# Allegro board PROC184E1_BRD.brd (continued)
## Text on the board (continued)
User.21: TP26 | C479 | C459 | B | TP49 | R304 | R309 | R315 | R294 | R298 | R283 | R281 | R257 | R259 | R276 | R267 | R270 | R273 | R264 | R261 | R311 | FL26 | R258 | R302 | R275 | R268 | R282 | R1292 | R260 | FL27 | TP142 | A | TP146 | R414 | C | R428 | U77 | U70 | FL33 | FL34 | FL35 | FL24 | FL25 | FL32 | TP137 | U53 | TP166 | FL23 | TP132 | TP149 | R351 | U74 | TP191 | U66 | R541 | TP192 | U110 | TP197 | U104 | TP189 | TP152 | FL43 | TP116 | D36 | R470 | TP120 | FL44 | TP165 | TP160 | FL45 | FL42 | TP122 | C285 | FL46 | TP155 | D19 | TP239 | FL6 | D20 | FL1 | D13 | D14 | Y3 | D15 | D16 | TP256 | U137 | TP227 | TP222 | L37 | FL53 | FL50 | D | FL54 | FL51 | TP180 | TP185 | FL55 | FL52 | U129 | U95 | U85 | TP131 | TP315 | TP124 | TP128 | U96 | TP147 | TP115 | TP220 | R396 | R400 | R404 | R391 | TP205 | R386 | R378 | TP123 | C352 | TP186 | L30 | TP221 | U117 | FL47 | TP187 | C330 | C336 | TP38 | C340 | C343 | C260 | C293 | U118 | C323 | FL48 | C261 | C294 | U120 | TP225 | TP145 | TP210 | TP209 | TP218 | TP216 | TP194 | TP195 | TP181 | TP174 | TP153 | TP127 | TP150 | TP129 | TP125 | J48 | TP143 | U106 | U83 | U100 | U115 | U93 | U99 | U84 | U94 | TP251 | LD11 | U57 | U65 | U64 | U61 | U60 | U56 | U32 | U31 | TP34 | TP75 | TP35 | TP23 | TP248 | LD12 | TP224 | L29 | TP226 | Q2 | C115 | R142 | R144 | R143 | R137 | R644 | R656 | R665 | R675 | C450 | C487 | C465 | R642 | R674 | R651 | R691 | C526 | R224 | R227 | R212 | R238 | R217 | R233 | R672 | R625 | R632 | R636 | C491 | C186 | C190 | C196 | R695 | C191 | C197 | C187 | C188 | R218 | R211 | R239 | R231 | R287 | R291 | C166 | R230 | R236 | R242 | R225 | R422 | R419 | R214 | R246 | C162 | U102 | R420 | R423 | C163 | U79 | R384 | R379 | R213 | R417 | R390 | R385 | R567 | R561 | R220 | R397 | R392 | R517 | R506 | R413 | U107 | R526 | R409 | R542 | R552 | C282 | R342 | R324 | C382 | R569 | R566 | C346 | R584 | R523 | C247 | R513 | R500 | C322 | R401 | C296 | R437 | C283 | C255 | C291 | R519 | C274 | R533 | U75 | R406 | C292 | R507 | R540 | R424 | U63 | R518 | C256 | R477 | C327 | R425 | R368 | C75 | R527 | C284 | R426 | C347 | C89 | R516 | C83 | R131 | R508 | C78 | R458 | C268 | R440 | R402 | R446 | C262 | R134 | R138 | R115 | R119 | R124 | C105 | R399 | R336 | R129 | R74 | R130 | R75 | R127 | R135 | R141 | R120 | R235 | C192 | C57 | R611 | R128 | R643 | R684 | C98 | C104 | C102 | C81 | C71 | C67 | C485 | C492 | C486 | C493 | R44 | C427 | R45 | C23 | R627 | C494 | R613 | R626 | R619 | C455 | C451 | U142 | R671 | C277 | C267 | C271 | C281 | C286 | C288 | R534 | C403 | R521 | R615 | R535 | R631 | R618 | R591 | R205 | R201 | R274 | R278 | R284 | R293 | R299 | R307 | R317 | R322 | R504 | R512 | R524 | R588 | R593 | R186 | C158 | R206 | C435 | C426 | C446 | C387 | U89 | U139 | C438 | C388 | C331 | C389 | R528 | C390 | C391 | C392 | C480 | R398 | R592 | R509 | R555 | R520 | R583 | R558 | R562 | R579 | R551 | R601 | U156 | C324 | C348 | C358 | C366 | C380 | C386 | C371 | C398 | C395 | R408 | R359 | R393 | R370 | R388 | C250 | C263 | C272 | C257 | C251 | C269 | R701 | R725 | C145 | R118 | R473 | C94 | C146 | C121 | R148 | C111 | C117 | R133 | R279 | R255 | C217 | C221 | R271 | R253 | C234 | C202 | R727 | R277 | R252 | C201 | R702 | C232 | R585 | U123 | C420 | R623 | R663 | R652 | R660 | R612 | R568 | R590 | R661 | R653 | R664 | R673 | C503 | C506 | C475 | R263 | TP102 | R363 | TP109 | TP103 | R364 | TP110 | TP104 | TP111 | R365 | TP105 | TP112 | R366 | TP106 | R367 | TP107 | TP113 | TP157 | TP177 | U69 | R382 | TP206 | TP144 | R415 | TP156 | R333 | R334 | R335 | TP139 | R432 | TP117 | R377 | TP162 | TP163 | TP161 | R480 | FL3 | FL4 | TP24 | TP17 | TP18 | C416 | C461 | C44 | L14 | C45 | C37 | L11 | C38 | D25 | C46 | L16 | C47 | D26 | C39 | L12 | C40 | D27 | C51 | L18 | C52 | D28 | TP237 | U128 | TP183 | TP173 | FL10 | TP134 | TP308 | R369 | C453 | TP141 | TP184 | R429 | FL11 | TP310 | TP130 | U116 | TP198 | TP199 | C359 | FL12 | C361 | U119 | C360 | TP200 | TP188 | FL13 | TP201 | TP202 | U121 | TP203 | TP213 | C341 | C335 | TP243 | TP172 | TP178 | TP136 | TP138 | TP118 | U114 | U105 | C205 | C223 | C194 | C238 | C195 | C239 | TP246 | D34 | D35 | C118 | R145 | R666 | R657 | R69 | R146 | C488 | C452 | R685 | R692 | C447 | C504 | C505 | C184 | R229 | R219 | R248 | R240 | R221 | R210 | C167 | R416 | C168 | C169 | R556 | R1299 | C362 | C363 | C325 | C364 | R543 | R434 | R489 | R447 | R490 | R491 | C264 | C258 | C396 | C313 | R410 | U62 | C326 | R1297 | R493 | C266 | R1295 | R494 | C393 | C297 | R421 | R532 | C381 | R495 | C373 | R407 | R452 | R438 | C265 | R457 | C276 | C279 | R444 | R395 | C270 | R122 | C85 | C72 | R123 | C61 | C86 | C73 | C74 | C87 | C62 | C56 | R121 | R607 | R76 | C90 | C99 | R641 | C417 | C462 | R676 | R723 | R724 | C537 | C463 | R677 | R711 | R712 | R645 | C530 | U134 | R646 | R71 | R647 | R658 | R679 | C55 | C415 | R659 | U127 | C468 | C469 | R680 | R624 | R100 | R101 | R102 | R103 | R104 | R105 | R106 | R544 | R107 | C349 | R108 | C350 | R109 | C351 | C334 | R595 | R505 | R620 | R600 | R580 | C405 | C383 | R511 | U122 | C384 | R614 | C275 | R1300 | C400 | C385 | R208 | U131 | R203 | U124 | C155 | R570 | C454 | R194 | R195 | R571 | R196 | C338 | R531 | R197 | R572 | R573 | R667 | R545 | R668 | R574 | R546 | R669 | R547 | R670 | C354 | R575 | C353 | R538 | C445 | C456 | C519 | C525 | C510 | R703 | C337 | R412 | C512 | C513 | C514 | C306 | R178 | C95 | R179 | R125 | R117 | C302 | C308 | C523 | C103 | C509 | C511 | R244 | R704 | R288 | R245 | U46 | C515 | R289 | C516 | C517 | C222 | R254 | R272 | C219 | C460 | C490 | R589 | R606 | U130 | U113 | R578 | C404 | C421 | U22 | J21 | TP29 | J16 | J18 | J19 | TP19 | TP63 | J13 | TP241 | TP6 | TP242 | TP9 | J12 | J22 | TP25 | TP179 | TP190 | J29 | Q1 | SW3 | SW4 | SW8 | TP288 | TP148 | TP249 | SW13 | TP182 | TP69 | TP71 | J1 | TP140 | C545 | C518 | TP57 | TP53 | TP44 | U109 | TP66 | TP64 | U141 | TP321 | TP82 | TP78 | TP84 | TP72 | TP16 | TP196 | TP65 | TP60 | TP324 | TP58 | TP154 | C149 | LD1 | LD6 | TP247 | C170 | TP135 | TP10 | C544 | J14 | J17 | TP85 | TP90 | L8 | TP217 | TP193 | C42 | C484 | J5 | TP212 | TP233 | U43 | U58 | U50 | TP231 | TP40 | SW7 | SW11 | TP121 | TP126 | R327 | R328 | R339 | TP230 | L20 | TP96 | Y4 | TP168 | TP28 | TP323 | TP240 | R550 | TP33 | TP70 | TP77 | TP211 | TP235 | TP51 | J10 | TP208 | TP229 | Y2 | R525 | U42 | U48 | J39 | FL22 | L19 | TP98 | L27 | L28 | U126 | U140 | R303 | FL5 | R292 | D17 | TP232 | R310 | TP81 | D18 | TP62 | R297 | TP93 | TP47 | Y5 | U23 | Y1 | TP50 | TP236 | Y6 | TP228 | C193 | TP61 | J40 | R243 | TP255 | TP56 | TP219 | TP67 | TP234 | U41 | TP250 | TP52 | U125 | U138 | J41 | J9 | ACC* | J2 | U3 | D5 | FL49 | SW2 | D6 | J4 | U5 | D7 | D8 | TP59 | TP204 | U4 | U7 | TP27 | C2 | TP21 | TP76 | TP79 | TP80 | TP83 | TP87 | TP94 | TP97 | TP100 | TP151 | R439 | D30 | TP22 | TP238 | R136 | L4 | C3 | TP167 | R352 | C328 | L24 | U35 | TP170 | R6 | TP101 | L33 | C101 | C112 | C120 | C126 | FL40 | C4 | C5 | C84 | U68 | U8 | U1 | FL41 | TP4 | L25 | TP1 | U36 | L31 | L34 | TP86 | Y8 | L32 | TP30 | TP14 | R53 | TP289 | U30 | C106 | C116 | R338 | TP99 | U37 | U27 | U24 | TP223 | TP95 | TP32 | TP244 | TP36 | C172 | J3 | U81 | TP322 | Y7 | R181 | U16 | J49 | C173 | TP20 | C280 | C174 | U145 | U21 | TP207 | TP31 | L35 | TP108 | J7 | TP133 | L23 | C290 | C295 | U51 | J47 | D29 | J37 | U45 | U49 | SW16 | R418 | C130 | C80 | C248 | TP325 | TP37 | C199 | C235 | SW14 | SW15 | LD9 | SW10 | SW12 | LD8 | SW6 | SW5 | SW9 | SW1 | LD7 | R290 | R321 | R314 | R249 | R22 | R222 | U29 | R132 | C43 | U19 | U10 | R394 | R383 | R343 | R361 | R389 | R356 | R373 | R376 | R350 | C50 | R52 | C54 | R329 | R340 | R374 | R354 | R300 | R305 | R285 | R295 | R312 | R325 | R380 | R347 | R319 | R387 | R371 | J27 | R602 | R232 | R241 | R596 | U2 | C522 | C543 | R360 | U72 | R296 | R326 | R286 | R313 | R320 | R301 | R306 | R330 | R597 | R341 | R375 | R348 | R355 | R372 | R381 | C204 | U47 | C499 | R678 | C440 | C24 | R640 | U6 | R598 | R256 | R700 | U34 | R576 | R581 | C466 | C474 | R155 | R599 | R605 | R152 | R23 | C29 | C508 | R582 | R577 | R5 | R7 | U14 | C34 | R92 | C63 | C259 | C66 | R705 | R405 | R280 | R46 | R200 | R204 | R403 | U39 | C376 | R411 | R430 | R435 | R441 | R450 | R454 | R460 | R467 | R474 | R483 | R496 | R502 | R514 | R529 | R536 | R548 | R553 | C33 | C21 | U154 | U38 | R182 | C177 | U103 | C433 | U112 | R183 | R564 | C370 | R698 | R610 | R693 | C11 | R616 | R346 | C12 | U40 | R475 | C467 | R699 | R20 | R694 | C224 | C233 | U108 | C231 | R266 | R442 | R484 | R436 | R497 | R537 | R549 | R431 | R503 | R515 | R530 | R455 | R461 | R468 | R554 | R451 | R25 | R27 | R31 | R47 | R48 | R51 | C19 | R560 | R79 | R12 | U92 | C76 | C365 | U11 | R223 | R228 | C189 | R94 | R216 | R234 | C355 | R269 | C226 | R262 | R265 | U86 | U97 | R81 | R337 | R89 | C171 | R316 | R935 | C77 | R82 | R349 | C442 | C436 | C397 | C41 | R318 | R654 | C36 | C218 | C200 | C236 | C175 | R649 | R621 | R629 | R50 | R55 | C135 | R114 | R126 | U67 | U101 | C127 | C131 | R344 | R933 | U111 | C249 | R353 | R358 | C203 | C220 | C225 | C237 | C79 | R42 | C443 | C437 | C152 | C157 | R43 | R655 | R622 | R630 | R650 | R67 | R209 | C159 | C151 | R68 | U90 | R1298 | C399 | C439 | C147 | C148 | C153 | U148 | C408 | R639 | R648 | R198 | U59 | U155 | C91 | U20 | U149 | J42 | R176 | R166 | U91 | U18 | R72 | R167 | R706 | R177 | C107 | C119 | C113 | U12 | R13 | R9 | C495 | U150 | J43 | R14 | C315 | C307 | R707 | U26 | U151 | J44 | C496 | C309 | C227 | C402 | U54 | U71 | C311 | C228 | R708 | C310 | C229 | R557 | C319 | R10 | C230 | C312 | U152 | J45 | C497 | C320 | R78 | R709 | C82 | R448 | U153 | J46 | C498 | R662 | C253 | C299 | C8 | R710 | U52 | C6 | R28 | U147 | C298 | C521 | C254 | U87 | C1 | R728 | C7 | C500 | R18 | R24 | R26 | C20 | R1 | R2 | R433 | R3 | U80 | R4 | U76 | R154 | R453 | R459 | R471 | C122 | C244 | C242 | C241 | R323 | C100 | C329 | C314 | R481 | R635 | R729 | C318 | U143 | C501 | U25 | C441 | C301 | C481 | U88 | C502 | R464 | C449 | R501 | R488 | R482 | C407 | R510 | U157 | C410 | U28 | U98 | R207 | R184 | R215 | J38 | J11 | J20 | J15 | J31 | TP91 | TP92 | R90 | R96 | R139 | J28 | R140 | J23 | TP5 | TP3 | D33 | TP2 | C432 | D37 | TP39 | TP11 | TP7 | TP68 | TP12 | TP8 | U73 | TP164 | TP13 | R463 | FL59 | R456 | R478 | L1 | R445 | U135 | U146 | C434 | TP245 | TP48 | U136 | FL56 | R345 | C32 | FL8 | C25 | C531 | FL57 | FL58 | FL9 | TP89 | TP15 | R185 | R1293 | TP88 | R332 | L13 | FL2 | TP41 | TP45 | R926 | D9 | TP46 | TP42 | L9 | TP43 | D10 | TP54 | D21 | C243 | L15 | TP55 | D22 | R226 | D11 | L10 | FL36 | D12 | D23 | L17 | FL37 | D24 | FL38 | C134 | FL39 | FL7 | U133 | D39 | R172 | R173 | R174 | R175 | R113 | R112 | L2 | D1 | D3 | L5 | TP175 | TP176 | L7 | FL28 | L6 | FL29 | TP171 | TP214 | R485 | FL30 | TP215 | D4 | FL31 | D2 | L3 | R180 | TP73 | TP159 | C28 | TP74 | TP158 | C9 | C10 | L36 | TP169 | FL14 | FL15 | C278 | C92 | R362 | R165 | FL16 | LD2 | FL17 | LD10 | TP119 | FL18 | TP114 | LD3 | R427 | FL19 | LD4 | L26 | L21 | L22 | LD5 | FL20 | D32 | D31 | FL21 | F2 | C53 | D38 | R187 | F1 | U44 | R357 | R308 | R449 | J24 | J26 | R91 | R95 | C128 | R60 | C31 | R15 | R156 | R19 | R61 | R116 | C18 | J25 | R62 | C143 | R49 | R63 | C144 | R64 | C15 | C93 | R202 | C16 | C160 | C60 | C17 | R157 | R689 | C303 | R633 | C59 | C14 | R158 | R476 | R637 | R686 | R84 | R159 | R70 | R690 | R634 | C13 | R160 | C448 | R147 | U13 | C377 | R603 | R85 | R161 | R199 | C48 | C378 | R86 | R162 | R604 | R87 | C379 | R163 | U78 | C444 | R164 | C289 | C304 | U15 | R617 | C216 | R462 | R17 | C125 | R83 | C129 | R77 | R153 | C411 | R54 | R73 | C412 | C527 | C520 | C473 | C413 | U9 | C414 | C161 | R250 | C401 | U33 | C406 | R628 | R251 | C482 | R608 | R638 | R565 | R609 | C483 | R559 | C507 | R687 | C528 | U132 | C529 | C164 | C49 | R688 | C165 | R58 | C369 | C524 | R59 | R697 | R88 | C245 | R247 | C246 | C198 | C476 | C422 | C477 | C423 | C478 | C30 | C65 | U17 | R99 | C96 | R586 | C109 | C409 | R696 | R587 | C110 | C97 | R563 | C394 | C470 | C367 | C344 | C332 | C424 | C471 | C425 | U55 | C375 | C356 | C472 | R331 | C22 | C136 | C137 | C185 | R65 | C138 | C176 | R66 | C139 | C140 | C141 | R237 | R726 | C142 | C206 | C418 | C207 | C464 | C419 | C208 | J32 | C532 | C209 | R713 | C210 | R97 | C64 | R714 | R98 | C211 | C538 | C132 | J33 | C533 | R56 | R169 | R171 | C212 | R29 | C133 | R715 | R30 | R168 | R170 | R57 | C213 | R716 | C35 | C345 | C368 | R32 | R33 | C539 | C214 | J34 | C374 | C357 | C333 | R34 | C534 | R35 | R681 | R36 | C215 | R37 | R717 | R38 | R718 | R39 | R21 | R594 | R40 | C540 | J35 | R41 | C535 | R682 | R8 | R80 | R719 | R16 | R720 | C240 | C541 | J36 | C178 | C536 | R683 | C68 | C26 | C69 | R721 | C70 | R722 | C27 | R93 | C179 | C542 | C180 | C58 | R486 | C154 | R188 | R189 | R487 | R11 | R190 | C181 | C273 | C317 | R469 | C430 | C182 | R443 | U144 | C156 | C428 | R191 | C300 | R472 | R192 | R479 | R193 | U82 | C183 | C489 | C458 | J6 | C316 | R499 | C114 | C305 | C108 | R498 | R149 | R465 | R522 | R466 | R150 | R110 | C339 | C321 | C150 | R151 | R111 | C123 | C88 | R492 | C457 | C342 | C431 | C429 | R539 | C372 | C252 | J30 | J8 | C124 | TOP ASSEMBLY | TDA4AP, TDA4VP, TDA4AH, & TDA4VH TOP ASSEMBLY REV.E2
User.22: U228 | TP320 | TP311 | TP314 | TP319 | TP294 | TP296 | TP306 | TP307 | TP316 | TP317 | TP305 | TP303 | TP304 | TP309 | R1092 | G | C1210 | U260 | TP318 | FL194 | C1031 | R980 | FL162 | C920 | FL151 | F | R1039 | FL150 | R1027 | R1037 | R1022 | R1049 | FL175 | FL176 | FL89 | TP258 | FL88 | FL87 | FL67 | TP287 | FL86 | TP282 | C695 | C697 | FL85 | C684 | R1148 | R1154 | C694 | TP285 | D | R877 | FL84 | R892 | E | R886 | C683 | R876 | TP266 | TP272 | R906 | R900 | R905 | R899 | TP262 | TP261 | TP292 | TP291 | FL122 | FL137 | FL153 | FL154 | FL158 | FL163 | R1102 | R1086 | R1060 | R1094 | R1076 | R761 | R768 | R762 | R767 | R1101 | R1093 | R1075 | R1085 | R1059 | R1056 | R821 | C1020 | C1237 | R1078 | C1202 | R1237 | R1088 | R1055 | R1095 | C1193 | R1226 | R1276 | C1234 | R1279 | C1242 | R1077 | R1087 | R1230 | R1236 | C1201 | C1230 | R1229 | R1108 | R1107 | R1112 | R1109 | C1203 | R898 | R904 | R1126 | C1198 | C1191 | R991 | R1053 | R1015 | R1110 | R1036 | R977 | R1091 | R1106 | R975 | R983 | R1048 | R1013 | R1084 | C1065 | R1031 | R1159 | C1086 | C1079 | R1104 | R1261 | R1245 | C1169 | U241 | R1221 | R1249 | R1254 | R1224 | R1235 | R1232 | R1256 | C1204 | U254 | R1103 | C1176 | R1187 | C1182 | R1194 | C966 | C975 | C1002 | C989 | C965 | C974 | C1027 | C1034 | R909 | R925 | R929 | R918 | C1197 | C1190 | R979 | R981 | R984 | C960 | R1097 | C1067 | R1016 | C1021 | C1042 | C1032 | C1070 | C968 | C940 | C925 | C1045 | R1105 | R1100 | R1090 | R1166 | C901 | C918 | C930 | C1041 | C1026 | C1036 | R1260 | C939 | R1246 | C938 | R1231 | R1234 | R1220 | R1223 | R1250 | R1253 | R1255 | R1165 | C1018 | C758 | C869 | C826 | C841 | C857 | C889 | R864 | R874 | C757 | C856 | C903 | U201 | C852 | C843 | R858 | C756 | R852 | C755 | C1113 | C1119 | C1107 | C754 | C1160 | R1176 | C753 | C1159 | C752 | C1158 | C828 | R896 | C818 | C820 | C849 | C813 | C1152 | R895 | C609 | C612 | C620 | C631 | C819 | C610 | C936 | C915 | R888 | C954 | C934 | C953 | R887 | R806 | R804 | C948 | C981 | C952 | C933 | C914 | C979 | C913 | R1064 | R1054 | C978 | C912 | C1015 | C1025 | R967 | C1035 | R976 | R1233 | R1241 | C786 | R961 | C825 | C842 | C853 | C888 | C887 | R973 | R974 | C799 | C895 | C798 | C854 | C904 | C1003 | C855 | C868 | C961 | FL170 | FL177 | FL179 | FL192 | FL100 | FL109 | FL116 | FL124 | FL156 | FL131 | FL102 | FL123 | FL115 | FL103 | FL127 | FL135 | FL113 | FL110 | FL112 | FL105 | FL111 | FL120 | FL145 | FL126 | FL104 | FL117 | FL144 | FL168 | FL119 | FL178 | FL125 | FL143 | FL133 | FL191 | FL182 | FL171 | FL165 | FL174 | FL166 | FL184 | FL183 | FL181 | FL180 | FL169 | FL173 | C970 | C986 | C992 | C972 | C999 | C851 | C943 | C898 | C859 | C893 | C865 | C874 | C861 | C873 | C845 | C866 | C881 | C947 | C962 | C998 | C983 | C987 | C997 | FL159 | C944 | C996 | C946 | C1008 | C964 | FL114 | FL140 | CARD EJECTED | CARD LOCK | CARD OVER STROCK | C1166 | R1071 | R1070 | R1069 | R1068 | R1067 | R1066 | R1065 | R1074 | C1248 | TP279 | TP278 | R1141 | R1162 | R1214 | R1213 | R1136 | R1158 | R1202 | R1201 | R1212 | R1117 | R990 | R1011 | R1205 | R1116 | R989 | R1010 | R1118 | R1009 | R988 | R987 | R1008 | R1115 | R986 | R1007 | R1114 | R985 | R1006 | R997 | R1005 | R996 | R1004 | R995 | R1003 | R994 | R1002 | R993 | R1001 | R1000 | R992 | C700 | TP313 | TP312 | R1211 | R1210 | R1204 | FL193 | R1203 | R1023 | C665 | FL132 | R1209 | C664 | C663 | R1206 | FL81 | FL99 | FL76 | C662 | C750 | C661 | C660 | C659 | C749 | C658 | C731 | C657 | FL71 | C656 | C730 | C748 | FL70 | C729 | FL69 | C747 | C728 | FL141 | FL68 | C727 | C746 | FL197 | C726 | C745 | R938 | TP286 | C1094 | TP276 | C725 | C744 | FL66 | TP275 | C696 | C680 | TP269 | R868 | C679 | TP268 | C724 | C743 | FL65 | TP274 | TP267 | R867 | TP273 | FL83 | R885 | R891 | C742 | FL62 | C1093 | FL60 | C765 | FL94 | C764 | FL97 | C763 | FL96 | C762 | R1080 | R750 | R1032 | R1283 | R1239 | R1272 | R1238 | R1271 | R1282 | C1233 | R1275 | R1274 | R1273 | R1113 | R1073 | R1072 | C1064 | C1056 | C707 | C704 | R1242 | C1220 | C823 | C858 | C812 | C805 | C882 | C896 | C1073 | C988 | C1016 | C1052 | C931 | C951 | C1040 | C1219 | C1208 | C1180 | R1125 | R1160 | R1140 | C1120 | R1124 | R1218 | C1135 | R1139 | R1217 | R1200 | R1199 | R1119 | R1248 | R1207 | R1018 | C1009 | R1296 | R1244 | R1208 | C1196 | C1017 | C701 | C710 | C958 | C706 | C716 | C957 | C720 | C1030 | R910 | C1022 | C1028 | C1207 | R1216 | R1050 | C984 | R1046 | R1215 | R1198 | C950 | C911 | R1197 | C945 | C905 | C976 | C863 | C924 | C837 | C927 | C910 | C1062 | C1078 | C909 | C908 | R932 | C833 | C1048 | C832 | C921 | C831 | C1047 | C922 | C1046 | C822 | C1109 | C1125 | R930 | C1108 | C1121 | C1114 | C681 | C1128 | C1127 | C1088 | C1136 | C1153 | C1112 | C1129 | C1145 | R793 | C1077 | C1061 | C604 | C1076 | C751 | C642 | C641 | C601 | C605 | C640 | C639 | C638 | C600 | C637 | C619 | C636 | C618 | C635 | C617 | C634 | C616 | C633 | C615 | C632 | C935 | C614 | C613 | C709 | R1121 | C811 | C1010 | C808 | C807 | C790 | C788 | R966 | C1192 | R1240 | C836 | C830 | C829 | C847 | R972 | C862 | C871 | C824 | R971 | C821 | C835 | R969 | C834 | C848 | R968 | C864 | C1029 | C959 | C969 | C995 | C956 | FL139 | FL136 | FL108 | FL128 | FL121 | FL118 | FL147 | FL107 | FL148 | FL152 | FL160 | FL146 | FL130 | FL149 | FL142 | FL138 | FL129 | FL134 | FL157 | FL106 | FL155 | FL189 | FL190 | FL167 | FL172 | FL187 | FL186 | FL164 | FL188 | FL185 | C1014 | C1019 | C1012 | C993 | C1006 | C1005 | C1004 | C971 | C990 | C899 | C827 | C870 | C894 | C900 | C876 | C875 | C850 | C867 | C885 | C840 | C932 | C916 | C878 | C844 | C860 | C967 | C880 | C1013 | C1011 | C1007 | C991 | FL101 | D42 | D43 | C1229 | C1215 | Y9 | FL198 | R742 | R738 | C547 | TP260 | J54 | J56 | C1238 | C1227 | R962 | TP290 | R963 | R957 | C1240 | C1231 | L38 | U188 | U244 | U248 | U266 | U222 | U214 | U219 | U235 | U231 | U230 | U225 | Y13 | C647 | U203 | R1137 | R1138 | R1142 | R1145 | C653 | TP263 | TP264 | U262 | R1014 | J52 | U272 | TP257 | U193 | FL80 | FL78 | FL64 | FL73 | FL75 | U199 | U186 | TP293 | TP295 | Y12 | FL79 | C767 | FL72 | FL74 | FL77 | TP270 | TP265 | TP280 | TP283 | FL63 | U261 | U271 | C565 | R1146 | R1152 | U183 | TP326 | C560 | U174 | J51 | L39 | C549 | FL196 | Y11 | TP281 | TP284 | FL195 | C1087 | U164 | B1 | U194 | U185 | U162 | FL161 | C942 | TP271 | TP277 | R1044 | R1058 | D40 | C929 | C1060 | C629 | U216 | C928 | C1059 | U158 | U178 | U180 | U166 | TP253 | TP252 | R1057 | U172 | U210 | L43 | U211 | U212 | U207 | U208 | R1143 | R1147 | D41 | J57 | U179 | J55 | R1251 | R1247 | U237 | C1038 | C1055 | U240 | L42 | C678 | C602 | U223 | U224 | U238 | U239 | R756 | R770 | R784 | R789 | R751 | U205 | R1034 | R1038 | R1043 | R1047 | J53 | R741 | U170 | R827 | C554 | C598 | C611 | C1259 | C1265 | C655 | C1249 | C1250 | R826 | R811 | R813 | R944 | R1188 | U181 | C553 | R1155 | R1186 | R1153 | R1195 | C902 | U220 | C721 | U191 | U197 | U202 | U206 | R1042 | U200 | U249 | R999 | U159 | U267 | C596 | R937 | C1023 | U227 | R1177 | R1171 | R1168 | R955 | R922 | R1017 | R916 | U176 | R936 | R949 | C768 | R1161 | R1156 | R802 | R1222 | R779 | R1219 | R954 | R737 | R782 | C595 | U175 | C879 | C886 | C1089 | C1043 | R1180 | C1049 | C717 | C1063 | C1161 | C1082 | R1184 | U190 | U196 | U253 | C715 | R1144 | C1117 | U243 | U233 | R912 | C708 | C1131 | R1172 | R1181 | R1185 | R1170 | C1228 | R1225 | C1206 | C1200 | R781 | R787 | R772 | R740 | R1135 | C1097 | C567 | U257 | R921 | R917 | C723 | C573 | R765 | R1289 | R1291 | R1264 | C1096 | C1098 | C1118 | R856 | R1130 | C722 | C1095 | R1133 | C569 | U246 | R875 | R1045 | R1294 | R863 | R1288 | U245 | R1051 | C702 | C652 | C686 | C1080 | R836 | R1287 | R1290 | R866 | C771 | C761 | R844 | R758 | U168 | R755 | C759 | C732 | C733 | C685 | R760 | C711 | R769 | U187 | C1099 | C712 | R1286 | C581 | C570 | C1102 | C583 | R808 | C668 | R881 | R884 | R890 | R894 | R897 | C1100 | R1267 | C1209 | R757 | R880 | R883 | R889 | R893 | R754 | U167 | R791 | R759 | C646 | C588 | C1101 | R798 | R1174 | R862 | C1173 | C1103 | C1199 | R1173 | C644 | C651 | R807 | R803 | U256 | C1172 | R861 | C675 | R1167 | C585 | C677 | C1146 | C1110 | C1104 | R855 | C955 | U177 | C1033 | C1066 | C846 | C1054 | R843 | R835 | C982 | C1090 | C699 | R785 | C787 | R797 | R790 | R771 | R773 | R764 | C698 | C606 | C608 | C1068 | C1024 | C1044 | C1081 | C1074 | C872 | C806 | R730 | R919 | R805 | U173 | R911 | C1051 | R763 | U255 | U161 | C574 | C1037 | C1053 | C897 | C1069 | R1120 | R978 | R970 | R998 | U258 | R1012 | C795 | R783 | R788 | R794 | C1175 | C963 | C985 | R1033 | C789 | C892 | C1072 | R982 | R1081 | R734 | C548 | C1071 | C891 | C977 | C1174 | R1026 | C785 | R1035 | C571 | R744 | U165 | R731 | R753 | R964 | U213 | U259 | R739 | R732 | R1134 | R1179 | R1257 | C587 | C1232 | C586 | U242 | U270 | R1178 | C1251 | R1079 | R1089 | R1061 | C1122 | U234 | U276 | C797 | R1111 | R1123 | C1163 | C1252 | C1255 | C796 | C1165 | C1264 | U275 | C816 | C810 | R849 | R845 | R847 | C1164 | C1162 | R1266 | C815 | C809 | R1262 | C666 | R1228 | R956 | C1253 | C937 | C906 | R939 | U273 | U277 | U264 | R1227 | C1254 | C1256 | R1021 | R1024 | U268 | C603 | C607 | C667 | C1241 | U269 | C1058 | U274 | C1057 | D45 | D44 | C923 | C1263 | C1262 | R1099 | R1098 | C1211 | C1195 | C628 | C690 | C689 | C627 | C1194 | C626 | C688 | C625 | C687 | C624 | C623 | C622 | C621 | R1281 | R1280 | U189 | C558 | U218 | U221 | U215 | U229 | U226 | U236 | U232 | U204 | C1187 | C1181 | C674 | C673 | U192 | U198 | C1247 | C1186 | C1179 | TP259 | C682 | C566 | U169 | U263 | C713 | C649 | R923 | C672 | C648 | C671 | C580 | R809 | R810 | FL82 | R860 | R870 | R869 | R859 | C555 | U195 | U184 | FL93 | R1041 | R1020 | FL92 | R1040 | R1019 | FL61 | FL91 | FL90 | FL95 | R778 | R947 | R777 | R946 | R945 | R1096 | R1052 | U217 | FL98 | U265 | TP254 | C1001 | Y10 | L40 | U171 | TP302 | TP301 | R1150 | C1257 | TP300 | U209 | R1149 | C559 | U250 | TP299 | TP298 | TP297 | U182 | L41 | C1260 | C760 | C550 | J50 | C599 | C1123 | C551 | U252 | R736 | R735 | R812 | C1167 | R815 | R854 | R1252 | R1263 | U247 | R943 | R822 | C693 | C926 | C1138 | R942 | R1030 | R814 | R853 | R848 | R1029 | C1137 | R953 | R820 | R1129 | C692 | R1028 | R819 | R952 | C980 | R733 | U251 | R1025 | C552 | R1189 | R1128 | R873 | C1124 | C772 | C576 | C630 | R749 | R1157 | R951 | C691 | C597 | R903 | R825 | R872 | R959 | C654 | R824 | R934 | R958 | R823 | R871 | R882 | C1171 | C1168 | R941 | C1170 | R902 | R901 | R879 | R818 | C883 | U160 | R878 | C766 | C557 | C1177 | R920 | R1132 | R931 | R1265 | C589 | C593 | R928 | C564 | C592 | C1134 | C1189 | C563 | C591 | R927 | C590 | R1259 | C562 | C594 | C1226 | C1225 | C1224 | C645 | R842 | R841 | R840 | C703 | C670 | C669 | R865 | C1188 | C1218 | C1178 | R1258 | R776 | C1223 | C1222 | C1111 | C1221 | C1133 | C572 | C1147 | R786 | R1169 | C1106 | C1115 | C1148 | R766 | C582 | C1157 | C1140 | C777 | C773 | C1150 | C1156 | R914 | R1164 | C782 | C1141 | R913 | C1155 | R915 | R857 | C776 | C1139 | C719 | R1163 | C676 | C1154 | C775 | C1132 | C718 | C781 | C1151 | R924 | C774 | C780 | C779 | C778 | C579 | C1144 | R1175 | R839 | C1149 | R838 | C578 | R837 | C1143 | C577 | C584 | C737 | R775 | C561 | R796 | C1142 | C736 | U163 | R795 | C1116 | C1130 | C741 | R774 | C740 | C1126 | C556 | R799 | C739 | C738 | C884 | C814 | C735 | C784 | C734 | C1085 | C783 | C1084 | C792 | C1083 | C793 | C714 | C1092 | C1091 | C817 | C890 | C791 | C575 | C839 | C794 | R1127 | C877 | R965 | C1185 | R948 | R1193 | C838 | R792 | R1192 | R1191 | C1000 | R1190 | C1184 | C1183 | C1039 | C568 | C705 | R908 | R748 | R907 | C546 | R747 | C1212 | R1063 | R746 | C804 | C973 | C1213 | R752 | C769 | R1062 | C803 | R745 | C802 | R960 | R743 | C1217 | C770 | C994 | C917 | R1196 | C941 | C1243 | R801 | R800 | C1245 | R1183 | C800 | C801 | R1182 | C1075 | R1151 | C1258 | C1105 | C1235 | R1284 | R828 | R1122 | C1050 | R1270 | R817 | R1131 | R1269 | R834 | R816 | R1268 | R833 | C650 | C287 | R832 | R851 | R831 | R850 | R830 | R829 | C1236 | C643 | R846 | C1244 | C1216 | C1246 | C1261 | R950 | R940 | R1285 | C1214 | C1239 | R1278 | R1243 | R1277 | C919 | C949 | C1205 | R780 | R1083 | R1082 | C907 | BOTTOM ASSEMBLY | JTDA4AP, TDA4VP, TDA4AH, & TDA4VH BOTTOM ASSEMBLY REV.E2
User.23: TOP ASSEMBLY | PRIMARY-SIDE-SIG | 04 | TDA4AP, TDA4VP, TDA4AH, & TDA4VH TOP ASSEMBLY REV.E4
User.24: CARD EJECTED | CARD LOCK | CARD OVER STROCK | BOTTOM ASSEMBLY | SECONDARY-SIDE-SIG | 19 | JTDA4AP, TDA4VP, TDA4AH, & TDA4VH BOTTOM ASSEMBLY REV.E4
User.32: INNER-SIGNAL-6 | 17
User.33: GROUND-PLANE-06 | 18
User.34: GROUND-PLANE-6 | 18
User.35: GROUND-PLANE-05 | 16
User.36: GROUND-PLANE-5 | 16
User.37: INNER-SIGNAL-6 | 17
User.39: INNER-SIGNAL-05 | 15
User.45: B | A | C | D | G | BOARD NAME: | J742S2 EVALUATION MODULE | REV: E1 | DATE: 02/02/2024 | DESCRIPTION: | SHEET | 001 TOP ASSEMBLY | 003 BOTTOM ASSEMBLY | 001 BOTTOM ASSEMBLY | 003 TOP ASSEMBLY | 002 BOTTOM ASSEMBLY | 002 TOP ASSEMBLY | OF | 23 | PROC184 | SCALE: 1 | FIGURE | SIZE | 8.0 | 10.0 | 20.0 | 28.0 | 32.0 | 36.0 | 40.0 | 44.0 | 46.0 | 48.0 | 56.0 | 60.0 | 66.0 | 68.0 | 86.0 | 90.0 | 34.0 | 52.0 | 58.0 | 92.0 | 108.0 | 126.0 | 52.0x24.0 | 62.0x24.0 | 70.0x26.0 | 82.0x24.0 | 86.0x24.0 | 90.0x26.0 | 98.0x24.0 | 158.0x78.0 | DRILL CHART: TOP to BOTTOM | ALL UNITS ARE IN MILS | TOLERANCE | +3.0/-3.0 | +2.0/-2.0 | +1.969/-1.969 | PLATED | NON-PLATED | QTY | 5406 | 1 | 870 | 276 | 128 | 3 | 31 | 12 | 77 | 33 | 6 | 2 | 4 | 11 | 18 | 5.0 | DRILL CHART: TOP to L2-GND1 | DRILL CHART: L2-GND1 to L3-SIGNAL1 | DRILL CHART: L3-SIGNAL1 to L4-GND2 | DRILL CHART: L4-GND2 to L5-SIGNAL2 | DRILL CHART: L4-GND2 to L13-GND5 | DRILL CHART: L12-SIGNAL5 to L13-GND5 | DRILL CHART: L13-GND5 to L14-SIGNAL6 | DRILL CHART: L14-SIGNAL6 to L15-GND6 | DRILL CHART: L15-GND6 to BOTTOM | 1278 | 1044 | 593 | 342 | 306 | 618 | 999 | 1053 | 411 | TEXAS INSTRUMENTS | LAYER NAME | 0.0034 | 0.0038 | 0.005 | 0.0046 | 0.0052 | 13 | 14 | 09 | 10 | 20 | SL# | 01 | 02 | 03 | 04 | 05 | 06 | 07 | 19 | 21 | 24 | 08 | 22 | 25 | 26 | 16 | 15 | 17 | 27 | MICROSTRIP | STRIPLINE | EDGE COUPLED STRIPLINE | EDGE COUPLED MICROSTRIP | TYPE | L1/L16 | LAYER | L1 | L3,L14 | L5,L12 | L3 | L5 | L14 | L10 | L7 | L7,L10 | FINISHED Cu | 1.67oz | 0.5oz. | 1oz. | TRACEWIDTH(Mils) | 5.2 | 4.5 | 5 | 3.7 | 4.1 | 5.1 | 4.75 | 5.5 | 7 | 3.1 | 3.5 | 3.6 | 4.25 | 4.3 | 3.3 | 7.5 | X-SECTION | SPACING(Mils) | - | 15.5 | 8 | 7.3 | 5.8 | 6.9 | 6.5 | 8.3 | 9.7 | DIELECTRIC THICKNESS | IMPEDANCE(Ohms) | 85 | 80 | 66 | 100 | 90 | 100 DSI | 132 | 50 | 40 | 120 | [INCHES] | REF LAYER | L2/L13 | L2/L15 | L2/L4,L13/L15 | L2/L4 | L4/L6,L11/L13 | L4/L6 | L13/L15 | L9/L11 | L6/L8 | L6/L8,L9/L11 | L01 | L02 | L03 | L04 | L05 | L06 | L07 | L08 | L09 | L11 | L12 | L13 | L15 | L16 | PRIMARY SIDE | PRIMARY SIDE SILKSCREEN | PRIMARY SIDE SOLDERMASK | GROUND-PLANE-1 | INNER-SIGNAL-1 | GROUND-PLANE-2 | INNER-SIGNAL-2 | GROUND-PLANE-3 | INNER-SIGNAL-3 | POWER-PLANE-1 | POWER-PLANE-2 | INNER-SIGNAL-4 | GROUND-PLANE-4 | INNER-SIGNAL-5 | GROUND-PLANE-5 | INNER-SIGNAL-6 | GROUND-PLANE-6 | SECONDARY SIDE | SECONDARY SIDE SOLDERMASK | SECONDARY SIDE SILKSCREEN | LAYER STACKUP | IMPEDANCE SPECIFICATIONS
